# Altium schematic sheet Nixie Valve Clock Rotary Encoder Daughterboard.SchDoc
size A4; SheetNumber: 1; SheetTotal: 1
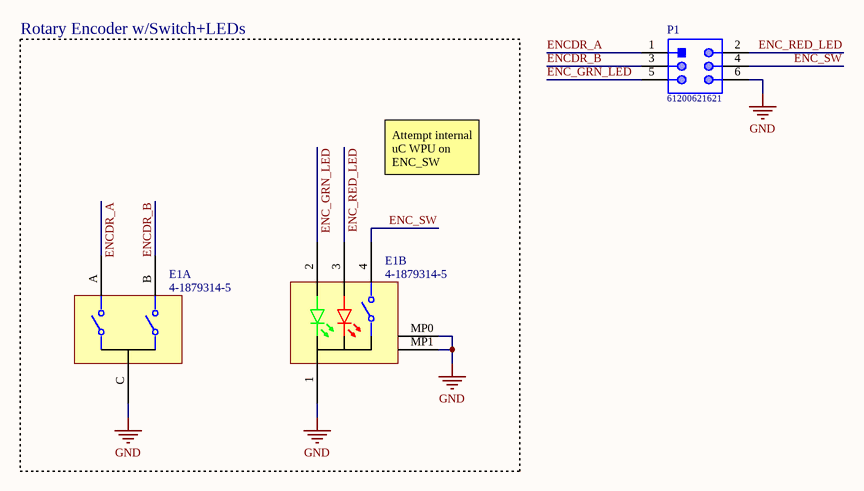
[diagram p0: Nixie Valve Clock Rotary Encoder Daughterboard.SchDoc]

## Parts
?  (no value)
E1  4-1879314-5  [4-1879314-5-Footprint-1]  (parts A,B of 2)
P1  61200621621  [61200621621]

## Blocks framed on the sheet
Rotary Encoder w/Switch+LEDs: E1

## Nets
GND: E1.1 E1.C E1.MP0(Mounting_Point_0) E1.MP1(Mounting_Point_1) P1.6
ENC_GRN_LED: E1.2(Green_LED) P1.5
ENC_RED_LED: E1.3(Red_LED) P1.2
ENC_SW: E1.4(Switch) P1.4
ENCDR_A: E1.A P1.1
ENCDR_B: E1.B P1.3

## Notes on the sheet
- Attempt internal uC WPU on ENC_SW

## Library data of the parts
? = CMP-00003-4: The KETS Schematic Sheet Title Block
E1 = CMP-010-00025-2: Incremental Encoder, Mechanical, 24Ppr Rohs Compliant: Yes; Max Supply Voltage: 5V; Number of Channels: 2; Pulses per Revolution: 24; Value: 25kΩ; Hole Diameter: 1.1mm
P1 = CMP-002-00109-1: Board Connector, 6 Contact(s), 2 Row(s), Male, Straight, Solder Terminal; Option: General Purpose; Number of Rows Loaded: 2; MIL Conformance: No; Number of Contacts: 6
